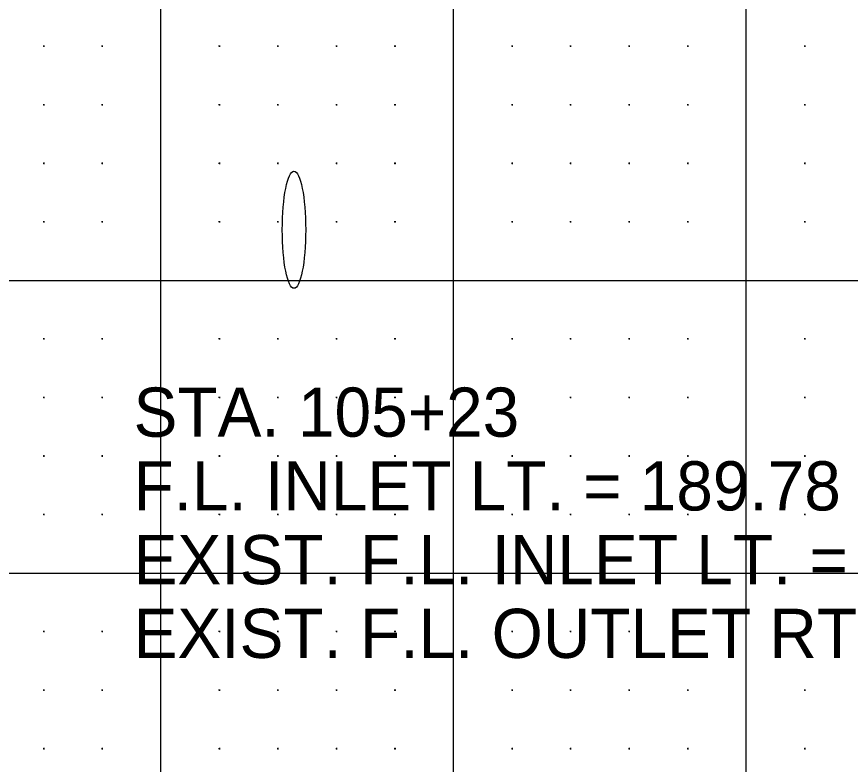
# Model space of a CAD drawing. Extents: x 471 to 2121, y 140 to 650.
# Drawn here: x 1111.4 to 1253.8, y 267.3 to 395.1 of the extents above; entities that cross this region are included whole.
import ezdxf

# ---------------------------------------------------------------- set-up
doc = ezdxf.new("R2010")
doc.units = 0
for name, color, linetype in [('Default', 7, 'Continuous'), ('DSN_DRFT_Border Grid', 7, 'Continuous'), ('S_BASELINE', 7, 'Continuous')]:
    doc.layers.add(name, color=color, linetype=linetype)

msp = doc.modelspace()

# ---------------------------------------------------------------- linework, layer by layer
at = {"layer": 'DSN_DRFT_Border Grid'}
for p, q in [((1136.06, 150), (1136.06, 650)), ((1136.06, 150), (1136.06, 650)), ((1186.06, 150), (1186.06, 650)), ((1186.06, 150), (1186.06, 650)), ((1236.06, 150), (1236.06, 650)), ((1236.06, 150), (1236.06, 650)), ((1116.18, 390), (1115.94, 390)), ((1116.18, 390), (1115.94, 390)), ((1116.06, 390.12), (1116.06, 389.88)), ((1116.06, 390.12), (1116.06, 389.88)), ((1126.18, 390), (1125.94, 390)), ((1126.18, 390), (1125.94, 390)), ((1126.06, 390.12), (1126.06, 389.88)), ((1126.06, 390.12), (1126.06, 389.88)), ((1146.18, 390), (1145.94, 390)), ((1146.18, 390), (1145.94, 390)), ((1146.06, 390.12), (1146.06, 389.88)), ((1146.06, 390.12), (1146.06, 389.88)), ((1156.18, 390), (1155.94, 390)), ((1156.18, 390), (1155.94, 390)), ((1156.06, 390.12), (1156.06, 389.88)), ((1156.06, 390.12), (1156.06, 389.88)), ((1166.18, 390), (1165.94, 390)), ((1166.18, 390), (1165.94, 390)), ((1166.06, 390.12), (1166.06, 389.88)), ((1166.06, 390.12), (1166.06, 389.88)), ((1176.18, 390), (1175.94, 390)), ((1176.18, 390), (1175.94, 390)), ((1176.06, 390.12), (1176.06, 389.88)), ((1176.06, 390.12), (1176.06, 389.88)), ((1196.18, 390), (1195.94, 390)), ((1196.18, 390), (1195.94, 390)), ((1196.06, 390.12), (1196.06, 389.88)), ((1196.06, 390.12), (1196.06, 389.88)), ((1206.18, 390), (1205.94, 390)), ((1206.18, 390), (1205.94, 390)), ((1206.06, 390.12), (1206.06, 389.88)), ((1206.06, 390.12), (1206.06, 389.88)), ((1216.18, 390), (1215.94, 390)), ((1216.18, 390), (1215.94, 390)), ((1216.06, 390.12), (1216.06, 389.88)), ((1216.06, 390.12), (1216.06, 389.88)), ((1226.18, 390), (1225.94, 390)), ((1226.18, 390), (1225.94, 390)), ((1226.06, 390.12), (1226.06, 389.88)), ((1226.06, 390.12), (1226.06, 389.88)), ((1246.18, 390), (1245.94, 390)), ((1246.18, 390), (1245.94, 390)), ((1246.06, 390.12), (1246.06, 389.88)), ((1246.06, 390.12), (1246.06, 389.88)), ((1116.18, 380), (1115.94, 380)), ((1116.18, 380), (1115.94, 380)), ((1116.06, 380.12), (1116.06, 379.88)), ((1116.06, 380.12), (1116.06, 379.88)), ((1126.18, 380), (1125.94, 380)), ((1126.18, 380), (1125.94, 380)), ((1126.06, 380.12), (1126.06, 379.88)), ((1126.06, 380.12), (1126.06, 379.88)), ((1146.18, 380), (1145.94, 380)), ((1146.18, 380), (1145.94, 380)), ((1146.06, 380.12), (1146.06, 379.88)), ((1146.06, 380.12), (1146.06, 379.88)), ((1156.18, 380), (1155.94, 380)), ((1156.18, 380), (1155.94, 380)), ((1156.06, 380.12), (1156.06, 379.88)), ((1156.06, 380.12), (1156.06, 379.88)), ((1166.18, 380), (1165.94, 380)), ((1166.18, 380), (1165.94, 380)), ((1166.06, 380.12), (1166.06, 379.88)), ((1166.06, 380.12), (1166.06, 379.88)), ((1176.18, 380), (1175.94, 380)), ((1176.18, 380), (1175.94, 380)), ((1176.06, 380.12), (1176.06, 379.88)), ((1176.06, 380.12), (1176.06, 379.88)), ((1196.18, 380), (1195.94, 380)), ((1196.18, 380), (1195.94, 380)), ((1196.06, 380.12), (1196.06, 379.88)), ((1196.06, 380.12), (1196.06, 379.88)), ((1206.18, 380), (1205.94, 380)), ((1206.18, 380), (1205.94, 380)), ((1206.06, 380.12), (1206.06, 379.88)), ((1206.06, 380.12), (1206.06, 379.88)), ((1216.18, 380), (1215.94, 380)), ((1216.18, 380), (1215.94, 380)), ((1216.06, 380.12), (1216.06, 379.88)), ((1216.06, 380.12), (1216.06, 379.88)), ((1226.18, 380), (1225.94, 380)), ((1226.18, 380), (1225.94, 380)), ((1226.06, 380.12), (1226.06, 379.88)), ((1226.06, 380.12), (1226.06, 379.88)), ((1246.18, 380), (1245.94, 380)), ((1246.18, 380), (1245.94, 380)), ((1246.06, 380.12), (1246.06, 379.88)), ((1246.06, 380.12), (1246.06, 379.88)), ((1116.18, 370), (1115.94, 370)), ((1116.18, 370), (1115.94, 370)), ((1116.06, 370.12), (1116.06, 369.88)), ((1116.06, 370.12), (1116.06, 369.88)), ((1126.18, 370), (1125.94, 370)), ((1126.18, 370), (1125.94, 370)), ((1126.06, 370.12), (1126.06, 369.88)), ((1126.06, 370.12), (1126.06, 369.88)), ((1146.18, 370), (1145.94, 370)), ((1146.18, 370), (1145.94, 370)), ((1146.06, 370.12), (1146.06, 369.88)), ((1146.06, 370.12), (1146.06, 369.88)), ((1156.18, 370), (1155.94, 370)), ((1156.18, 370), (1155.94, 370)), ((1156.06, 370.12), (1156.06, 369.88)), ((1156.06, 370.12), (1156.06, 369.88)), ((1166.18, 370), (1165.94, 370)), ((1166.18, 370), (1165.94, 370)), ((1166.06, 370.12), (1166.06, 369.88)), ((1166.06, 370.12), (1166.06, 369.88)), ((1176.18, 370), (1175.94, 370)), ((1176.18, 370), (1175.94, 370)), ((1176.06, 370.12), (1176.06, 369.88)), ((1176.06, 370.12), (1176.06, 369.88)), ((1196.18, 370), (1195.94, 370)), ((1196.18, 370), (1195.94, 370)), ((1196.06, 370.12), (1196.06, 369.88)), ((1196.06, 370.12), (1196.06, 369.88)), ((1206.18, 370), (1205.94, 370)), ((1206.18, 370), (1205.94, 370)), ((1206.06, 370.12), (1206.06, 369.88)), ((1206.06, 370.12), (1206.06, 369.88)), ((1216.18, 370), (1215.94, 370)), ((1216.18, 370), (1215.94, 370)), ((1216.06, 370.12), (1216.06, 369.88)), ((1216.06, 370.12), (1216.06, 369.88)), ((1226.18, 370), (1225.94, 370)), ((1226.18, 370), (1225.94, 370)), ((1226.06, 370.12), (1226.06, 369.88)), ((1226.06, 370.12), (1226.06, 369.88)), ((1246.18, 370), (1245.94, 370)), ((1246.18, 370), (1245.94, 370)), ((1246.06, 370.12), (1246.06, 369.88)), ((1246.06, 370.12), (1246.06, 369.88)), ((1116.18, 360), (1115.94, 360)), ((1116.18, 360), (1115.94, 360)), ((1116.06, 360.12), (1116.06, 359.88)), ((1116.06, 360.12), (1116.06, 359.88)), ((1126.18, 360), (1125.94, 360)), ((1126.18, 360), (1125.94, 360)), ((1126.06, 360.12), (1126.06, 359.88)), ((1126.06, 360.12), (1126.06, 359.88)), ((1146.18, 360), (1145.94, 360)), ((1146.18, 360), (1145.94, 360)), ((1146.06, 360.12), (1146.06, 359.88)), ((1146.06, 360.12), (1146.06, 359.88)), ((1156.18, 360), (1155.94, 360)), ((1156.18, 360), (1155.94, 360)), ((1156.06, 360.12), (1156.06, 359.88)), ((1156.06, 360.12), (1156.06, 359.88)), ((1166.18, 360), (1165.94, 360)), ((1166.18, 360), (1165.94, 360)), ((1166.06, 360.12), (1166.06, 359.88)), ((1166.06, 360.12), (1166.06, 359.88)), ((1176.18, 360), (1175.94, 360)), ((1176.18, 360), (1175.94, 360)), ((1176.06, 360.12), (1176.06, 359.88)), ((1176.06, 360.12), (1176.06, 359.88)), ((1196.18, 360), (1195.94, 360)), ((1196.18, 360), (1195.94, 360)), ((1196.06, 360.12), (1196.06, 359.88)), ((1196.06, 360.12), (1196.06, 359.88)), ((1206.18, 360), (1205.94, 360)), ((1206.18, 360), (1205.94, 360)), ((1206.06, 360.12), (1206.06, 359.88)), ((1206.06, 360.12), (1206.06, 359.88)), ((1216.18, 360), (1215.94, 360)), ((1216.18, 360), (1215.94, 360)), ((1216.06, 360.12), (1216.06, 359.88)), ((1216.06, 360.12), (1216.06, 359.88)), ((1226.18, 360), (1225.94, 360)), ((1226.18, 360), (1225.94, 360)), ((1226.06, 360.12), (1226.06, 359.88)), ((1226.06, 360.12), (1226.06, 359.88)), ((1246.18, 360), (1245.94, 360)), ((1246.18, 360), (1245.94, 360)), ((1246.06, 360.12), (1246.06, 359.88)), ((1246.06, 360.12), (1246.06, 359.88)), ((521.06, 350), (2071.06, 350)), ((521.06, 350), (2071.06, 350)), ((1116.18, 340), (1115.94, 340)), ((1116.18, 340), (1115.94, 340)), ((1116.06, 340.12), (1116.06, 339.88)), ((1116.06, 340.12), (1116.06, 339.88)), ((1126.18, 340), (1125.94, 340)), ((1126.18, 340), (1125.94, 340)), ((1126.06, 340.12), (1126.06, 339.88)), ((1126.06, 340.12), (1126.06, 339.88)), ((1146.18, 340), (1145.94, 340)), ((1146.18, 340), (1145.94, 340)), ((1146.06, 340.12), (1146.06, 339.88)), ((1146.06, 340.12), (1146.06, 339.88)), ((1156.18, 340), (1155.94, 340)), ((1156.18, 340), (1155.94, 340)), ((1156.06, 340.12), (1156.06, 339.88)), ((1156.06, 340.12), (1156.06, 339.88)), ((1166.18, 340), (1165.94, 340)), ((1166.18, 340), (1165.94, 340)), ((1166.06, 340.12), (1166.06, 339.88)), ((1166.06, 340.12), (1166.06, 339.88)), ((1176.18, 340), (1175.94, 340)), ((1176.18, 340), (1175.94, 340)), ((1176.06, 340.12), (1176.06, 339.88)), ((1176.06, 340.12), (1176.06, 339.88)), ((1196.18, 340), (1195.94, 340)), ((1196.18, 340), (1195.94, 340)), ((1196.06, 340.12), (1196.06, 339.88)), ((1196.06, 340.12), (1196.06, 339.88)), ((1206.18, 340), (1205.94, 340)), ((1206.18, 340), (1205.94, 340)), ((1206.06, 340.12), (1206.06, 339.88)), ((1206.06, 340.12), (1206.06, 339.88)), ((1216.18, 340), (1215.94, 340)), ((1216.18, 340), (1215.94, 340)), ((1216.06, 340.12), (1216.06, 339.88)), ((1216.06, 340.12), (1216.06, 339.88)), ((1226.18, 340), (1225.94, 340)), ((1226.18, 340), (1225.94, 340)), ((1226.06, 340.12), (1226.06, 339.88)), ((1226.06, 340.12), (1226.06, 339.88)), ((1246.18, 340), (1245.94, 340)), ((1246.18, 340), (1245.94, 340)), ((1246.06, 340.12), (1246.06, 339.88)), ((1246.06, 340.12), (1246.06, 339.88)), ((1116.18, 330), (1115.94, 330)), ((1116.18, 330), (1115.94, 330)), ((1116.06, 330.12), (1116.06, 329.88)), ((1116.06, 330.12), (1116.06, 329.88)), ((1126.18, 330), (1125.94, 330)), ((1126.18, 330), (1125.94, 330)), ((1126.06, 330.12), (1126.06, 329.88)), ((1126.06, 330.12), (1126.06, 329.88)), ((1146.18, 330), (1145.94, 330)), ((1146.18, 330), (1145.94, 330)), ((1146.06, 330.12), (1146.06, 329.88)), ((1146.06, 330.12), (1146.06, 329.88)), ((1156.18, 330), (1155.94, 330)), ((1156.18, 330), (1155.94, 330)), ((1156.06, 330.12), (1156.06, 329.88)), ((1156.06, 330.12), (1156.06, 329.88)), ((1166.18, 330), (1165.94, 330)), ((1166.18, 330), (1165.94, 330)), ((1166.06, 330.12), (1166.06, 329.88)), ((1166.06, 330.12), (1166.06, 329.88)), ((1176.18, 330), (1175.94, 330)), ((1176.18, 330), (1175.94, 330)), ((1176.06, 330.12), (1176.06, 329.88)), ((1176.06, 330.12), (1176.06, 329.88)), ((1196.18, 330), (1195.94, 330)), ((1196.18, 330), (1195.94, 330)), ((1196.06, 330.12), (1196.06, 329.88)), ((1196.06, 330.12), (1196.06, 329.88)), ((1206.18, 330), (1205.94, 330)), ((1206.18, 330), (1205.94, 330)), ((1206.06, 330.12), (1206.06, 329.88)), ((1206.06, 330.12), (1206.06, 329.88)), ((1216.18, 330), (1215.94, 330)), ((1216.18, 330), (1215.94, 330)), ((1216.06, 330.12), (1216.06, 329.88)), ((1216.06, 330.12), (1216.06, 329.88)), ((1226.18, 330), (1225.94, 330)), ((1226.18, 330), (1225.94, 330)), ((1226.06, 330.12), (1226.06, 329.88)), ((1226.06, 330.12), (1226.06, 329.88)), ((1246.18, 330), (1245.94, 330)), ((1246.18, 330), (1245.94, 330)), ((1246.06, 330.12), (1246.06, 329.88)), ((1246.06, 330.12), (1246.06, 329.88)), ((1116.18, 320), (1115.94, 320)), ((1116.18, 320), (1115.94, 320)), ((1116.06, 320.12), (1116.06, 319.88)), ((1116.06, 320.12), (1116.06, 319.88)), ((1126.18, 320), (1125.94, 320)), ((1126.18, 320), (1125.94, 320)), ((1126.06, 320.12), (1126.06, 319.88)), ((1126.06, 320.12), (1126.06, 319.88)), ((1146.18, 320), (1145.94, 320)), ((1146.18, 320), (1145.94, 320)), ((1146.06, 320.12), (1146.06, 319.88)), ((1146.06, 320.12), (1146.06, 319.88)), ((1156.18, 320), (1155.94, 320)), ((1156.18, 320), (1155.94, 320)), ((1156.06, 320.12), (1156.06, 319.88)), ((1156.06, 320.12), (1156.06, 319.88)), ((1166.18, 320), (1165.94, 320)), ((1166.18, 320), (1165.94, 320)), ((1166.06, 320.12), (1166.06, 319.88)), ((1166.06, 320.12), (1166.06, 319.88)), ((1176.18, 320), (1175.94, 320)), ((1176.18, 320), (1175.94, 320)), ((1176.06, 320.12), (1176.06, 319.88)), ((1176.06, 320.12), (1176.06, 319.88)), ((1196.18, 320), (1195.94, 320)), ((1196.18, 320), (1195.94, 320)), ((1196.06, 320.12), (1196.06, 319.88)), ((1196.06, 320.12), (1196.06, 319.88)), ((1206.18, 320), (1205.94, 320)), ((1206.18, 320), (1205.94, 320)), ((1206.06, 320.12), (1206.06, 319.88)), ((1206.06, 320.12), (1206.06, 319.88)), ((1216.18, 320), (1215.94, 320)), ((1216.18, 320), (1215.94, 320)), ((1216.06, 320.12), (1216.06, 319.88)), ((1216.06, 320.12), (1216.06, 319.88)), ((1226.18, 320), (1225.94, 320)), ((1226.18, 320), (1225.94, 320)), ((1226.06, 320.12), (1226.06, 319.88)), ((1226.06, 320.12), (1226.06, 319.88)), ((1246.18, 320), (1245.94, 320)), ((1246.18, 320), (1245.94, 320)), ((1246.06, 320.12), (1246.06, 319.88)), ((1246.06, 320.12), (1246.06, 319.88)), ((1116.18, 310), (1115.94, 310)), ((1116.18, 310), (1115.94, 310)), ((1116.06, 310.12), (1116.06, 309.88)), ((1116.06, 310.12), (1116.06, 309.88)), ((1126.18, 310), (1125.94, 310)), ((1126.18, 310), (1125.94, 310)), ((1126.06, 310.12), (1126.06, 309.88)), ((1126.06, 310.12), (1126.06, 309.88)), ((1146.18, 310), (1145.94, 310)), ((1146.18, 310), (1145.94, 310)), ((1146.06, 310.12), (1146.06, 309.88)), ((1146.06, 310.12), (1146.06, 309.88)), ((1156.18, 310), (1155.94, 310)), ((1156.18, 310), (1155.94, 310)), ((1156.06, 310.12), (1156.06, 309.88)), ((1156.06, 310.12), (1156.06, 309.88)), ((1166.18, 310), (1165.94, 310)), ((1166.18, 310), (1165.94, 310)), ((1166.06, 310.12), (1166.06, 309.88)), ((1166.06, 310.12), (1166.06, 309.88)), ((1176.18, 310), (1175.94, 310)), ((1176.18, 310), (1175.94, 310)), ((1176.06, 310.12), (1176.06, 309.88)), ((1176.06, 310.12), (1176.06, 309.88)), ((1196.18, 310), (1195.94, 310)), ((1196.18, 310), (1195.94, 310)), ((1196.06, 310.12), (1196.06, 309.88)), ((1196.06, 310.12), (1196.06, 309.88)), ((1206.18, 310), (1205.94, 310)), ((1206.18, 310), (1205.94, 310)), ((1206.06, 310.12), (1206.06, 309.88)), ((1206.06, 310.12), (1206.06, 309.88)), ((1216.18, 310), (1215.94, 310)), ((1216.18, 310), (1215.94, 310)), ((1216.06, 310.12), (1216.06, 309.88)), ((1216.06, 310.12), (1216.06, 309.88)), ((1226.18, 310), (1225.94, 310)), ((1226.18, 310), (1225.94, 310)), ((1226.06, 310.12), (1226.06, 309.88)), ((1226.06, 310.12), (1226.06, 309.88)), ((1246.18, 310), (1245.94, 310)), ((1246.18, 310), (1245.94, 310)), ((1246.06, 310.12), (1246.06, 309.88)), ((1246.06, 310.12), (1246.06, 309.88)), ((521.06, 300), (2071.06, 300)), ((521.06, 300), (2071.06, 300)), ((1116.18, 290), (1115.94, 290)), ((1116.18, 290), (1115.94, 290)), ((1116.06, 290.12), (1116.06, 289.88)), ((1116.06, 290.12), (1116.06, 289.88)), ((1126.18, 290), (1125.94, 290)), ((1126.18, 290), (1125.94, 290)), ((1126.06, 290.12), (1126.06, 289.88)), ((1126.06, 290.12), (1126.06, 289.88)), ((1146.18, 290), (1145.94, 290)), ((1146.18, 290), (1145.94, 290)), ((1146.06, 290.12), (1146.06, 289.88)), ((1146.06, 290.12), (1146.06, 289.88)), ((1156.18, 290), (1155.94, 290)), ((1156.18, 290), (1155.94, 290)), ((1156.06, 290.12), (1156.06, 289.88)), ((1156.06, 290.12), (1156.06, 289.88)), ((1166.18, 290), (1165.94, 290)), ((1166.18, 290), (1165.94, 290)), ((1166.06, 290.12), (1166.06, 289.88)), ((1166.06, 290.12), (1166.06, 289.88)), ((1176.18, 290), (1175.94, 290)), ((1176.18, 290), (1175.94, 290)), ((1176.06, 290.12), (1176.06, 289.88)), ((1176.06, 290.12), (1176.06, 289.88)), ((1196.18, 290), (1195.94, 290)), ((1196.18, 290), (1195.94, 290)), ((1196.06, 290.12), (1196.06, 289.88)), ((1196.06, 290.12), (1196.06, 289.88)), ((1206.18, 290), (1205.94, 290)), ((1206.18, 290), (1205.94, 290)), ((1206.06, 290.12), (1206.06, 289.88)), ((1206.06, 290.12), (1206.06, 289.88)), ((1216.18, 290), (1215.94, 290)), ((1216.18, 290), (1215.94, 290)), ((1216.06, 290.12), (1216.06, 289.88)), ((1216.06, 290.12), (1216.06, 289.88)), ((1226.18, 290), (1225.94, 290)), ((1226.18, 290), (1225.94, 290)), ((1226.06, 290.12), (1226.06, 289.88)), ((1226.06, 290.12), (1226.06, 289.88)), ((1246.18, 290), (1245.94, 290)), ((1246.18, 290), (1245.94, 290)), ((1246.06, 290.12), (1246.06, 289.88)), ((1246.06, 290.12), (1246.06, 289.88)), ((1116.18, 280), (1115.94, 280)), ((1116.18, 280), (1115.94, 280)), ((1116.06, 280.12), (1116.06, 279.88)), ((1116.06, 280.12), (1116.06, 279.88)), ((1126.18, 280), (1125.94, 280)), ((1126.18, 280), (1125.94, 280)), ((1126.06, 280.12), (1126.06, 279.88)), ((1126.06, 280.12), (1126.06, 279.88)), ((1146.18, 280), (1145.94, 280)), ((1146.18, 280), (1145.94, 280)), ((1146.06, 280.12), (1146.06, 279.88)), ((1146.06, 280.12), (1146.06, 279.88)), ((1156.18, 280), (1155.94, 280)), ((1156.18, 280), (1155.94, 280)), ((1156.06, 280.12), (1156.06, 279.88)), ((1156.06, 280.12), (1156.06, 279.88)), ((1166.18, 280), (1165.94, 280)), ((1166.18, 280), (1165.94, 280)), ((1166.06, 280.12), (1166.06, 279.88)), ((1166.06, 280.12), (1166.06, 279.88)), ((1176.18, 280), (1175.94, 280)), ((1176.18, 280), (1175.94, 280)), ((1176.06, 280.12), (1176.06, 279.88)), ((1176.06, 280.12), (1176.06, 279.88)), ((1196.18, 280), (1195.94, 280)), ((1196.18, 280), (1195.94, 280)), ((1196.06, 280.12), (1196.06, 279.88)), ((1196.06, 280.12), (1196.06, 279.88)), ((1206.18, 280), (1205.94, 280)), ((1206.18, 280), (1205.94, 280)), ((1206.06, 280.12), (1206.06, 279.88)), ((1206.06, 280.12), (1206.06, 279.88)), ((1216.18, 280), (1215.94, 280)), ((1216.18, 280), (1215.94, 280)), ((1216.06, 280.12), (1216.06, 279.88)), ((1216.06, 280.12), (1216.06, 279.88)), ((1226.18, 280), (1225.94, 280)), ((1226.18, 280), (1225.94, 280)), ((1226.06, 280.12), (1226.06, 279.88)), ((1226.06, 280.12), (1226.06, 279.88)), ((1246.18, 280), (1245.94, 280)), ((1246.18, 280), (1245.94, 280)), ((1246.06, 280.12), (1246.06, 279.88)), ((1246.06, 280.12), (1246.06, 279.88)), ((1116.18, 270), (1115.94, 270)), ((1116.18, 270), (1115.94, 270)), ((1116.06, 270.12), (1116.06, 269.88)), ((1116.06, 270.12), (1116.06, 269.88)), ((1126.18, 270), (1125.94, 270)), ((1126.18, 270), (1125.94, 270)), ((1126.06, 270.12), (1126.06, 269.88)), ((1126.06, 270.12), (1126.06, 269.88)), ((1146.18, 270), (1145.94, 270)), ((1146.18, 270), (1145.94, 270)), ((1146.06, 270.12), (1146.06, 269.88)), ((1146.06, 270.12), (1146.06, 269.88)), ((1156.18, 270), (1155.94, 270)), ((1156.18, 270), (1155.94, 270)), ((1156.06, 270.12), (1156.06, 269.88)), ((1156.06, 270.12), (1156.06, 269.88)), ((1166.18, 270), (1165.94, 270)), ((1166.18, 270), (1165.94, 270)), ((1166.06, 270.12), (1166.06, 269.88)), ((1166.06, 270.12), (1166.06, 269.88)), ((1176.18, 270), (1175.94, 270)), ((1176.18, 270), (1175.94, 270)), ((1176.06, 270.12), (1176.06, 269.88)), ((1176.06, 270.12), (1176.06, 269.88)), ((1196.18, 270), (1195.94, 270)), ((1196.18, 270), (1195.94, 270)), ((1196.06, 270.12), (1196.06, 269.88)), ((1196.06, 270.12), (1196.06, 269.88)), ((1206.18, 270), (1205.94, 270)), ((1206.18, 270), (1205.94, 270)), ((1206.06, 270.12), (1206.06, 269.88)), ((1206.06, 270.12), (1206.06, 269.88)), ((1216.18, 270), (1215.94, 270)), ((1216.18, 270), (1215.94, 270)), ((1216.06, 270.12), (1216.06, 269.88)), ((1216.06, 270.12), (1216.06, 269.88)), ((1226.18, 270), (1225.94, 270)), ((1226.18, 270), (1225.94, 270)), ((1226.06, 270.12), (1226.06, 269.88)), ((1226.06, 270.12), (1226.06, 269.88)), ((1246.18, 270), (1245.94, 270)), ((1246.18, 270), (1245.94, 270)), ((1246.06, 270.12), (1246.06, 269.88)), ((1246.06, 270.12), (1246.06, 269.88))]:
    msp.add_line(p, q, dxfattribs=at)
at = {"layer": 'S_BASELINE'}
msp.add_ellipse((1158.81, 358.65), major_axis=(0, -10), ratio=0.2, dxfattribs=at)

# ---------------------------------------------------------------- texts
at = {"layer": 'Default'}
for s, p in [('STA. 105+23', (1131.4, 323.3)), ('F.L. INLET LT. = 189.78', (1131.4, 310.7)), ('EXIST. F.L. INLET LT. = 189.73', (1131.4, 298.1)), ('EXIST. F.L. OUTLET RT. = 188.87', (1131.4, 285.5))]:
    msp.add_text(s, height=8.4, dxfattribs=at).set_placement(p)

doc.saveas('drawing.dxf')
